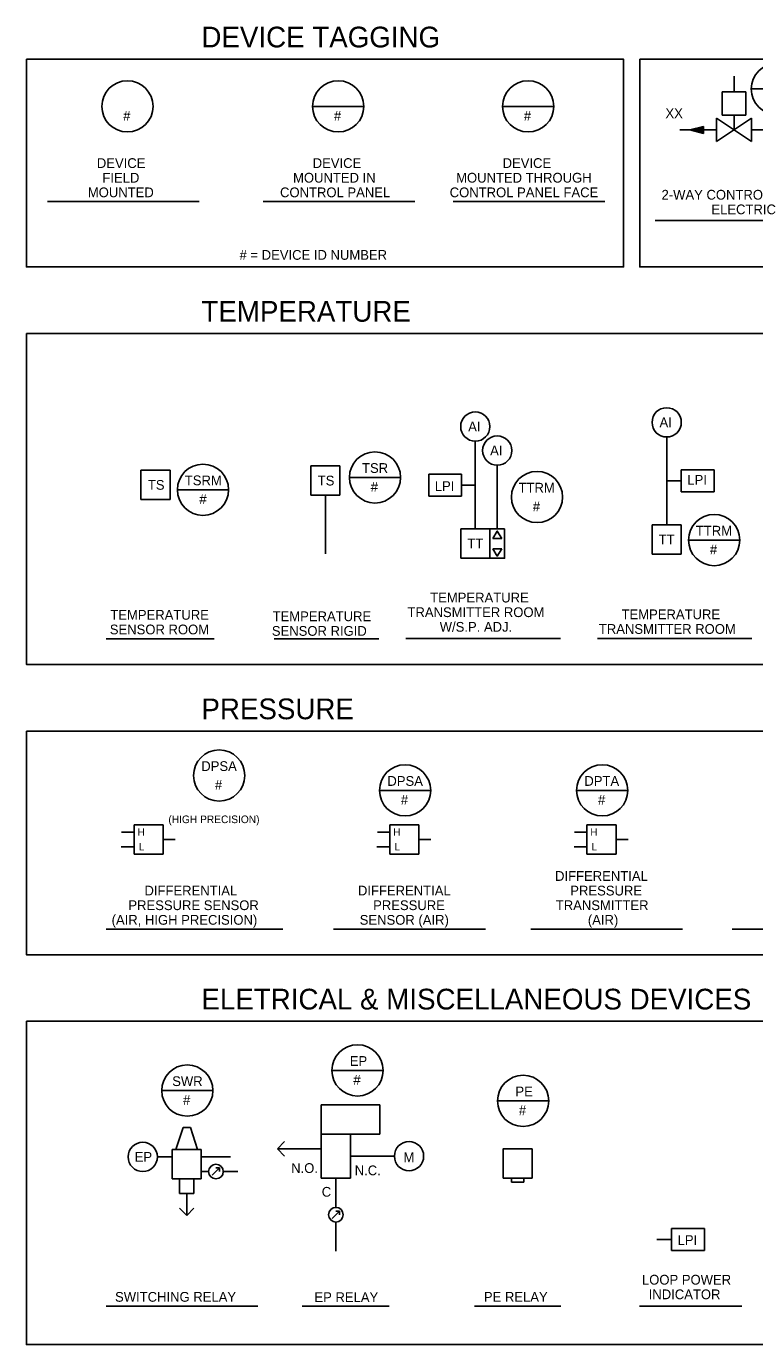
# Model space of a CAD drawing. Extents: x 10015 to 10283, y 10002 to 10184.
# Drawn here: x 10015.5 to 10065.3, y 10089.9 to 10180 of the extents above; entities that cross this region are included whole.
import ezdxf

# ---------------------------------------------------------------- set-up
doc = ezdxf.new("R2010")
doc.units = 0
for name, color, linetype in [('G-ANNO-TEXT', 7, 'Continuous'), ('G-DETL-LINE', 7, 'Continuous'), ('G-DETL-TEXT', 7, 'Continuous'), ('M-ANNO-NPLT', 7, 'Continuous')]:
    doc.layers.add(name, color=color, linetype=linetype)

msp = doc.modelspace()

# ---------------------------------------------------------------- linework, layer by layer
at = {"layer": 'G-ANNO-TEXT'}
for p, q in [((10016.93, 10168.02), (10027.299, 10168.02)), ((10031.683, 10168.02), (10042.051, 10168.02)), ((10044.663, 10168.02), (10055.032, 10168.02)), ((10058.48, 10166.726), (10071.068, 10166.726)), ((10020.949, 10138.131), (10028.33, 10138.131)), ((10032.443, 10138.131), (10039.578, 10138.131)), ((10041.442, 10138.166), (10052.007, 10138.166)), ((10054.521, 10138.166), (10065.086, 10138.166)), ((10020.949, 10118.291), (10033.029, 10118.291)), ((10036.499, 10118.291), (10046.867, 10118.291)), ((10049.974, 10118.291), (10060.342, 10118.291)), ((10063.729, 10118.291), (10074.097, 10118.291)), ((10020.949, 10092.522), (10031.317, 10092.522)), ((10034.344, 10092.522), (10040.291, 10092.522)), ((10046.125, 10092.522), (10052.027, 10092.522)), ((10057.408, 10092.522), (10064.404, 10092.522))]:
    msp.add_line(p, q, dxfattribs=at)
at = {"layer": 'G-DETL-LINE'}
for p, q in [((10063.063, 10173.927), (10063.063, 10175.527)), ((10063.063, 10175.527), (10064.663, 10175.527)), ((10064.663, 10175.527), (10064.663, 10173.927)), ((10062.663, 10173.725), (10065.063, 10172.125)), ((10062.663, 10172.125), (10062.663, 10173.725)), ((10062.663, 10172.125), (10065.063, 10173.725)), ((10063.063, 10173.927), (10064.663, 10173.927)), ((10063.863, 10173.927), (10063.863, 10172.925)), ((10065.063, 10173.725), (10065.063, 10172.125)), ((10062.663, 10172.925), (10060.153, 10172.925)), ((10061.768, 10172.92), (10060.835, 10172.92)), ((10061.768, 10172.961), (10061.013, 10172.961)), ((10061.768, 10172.878), (10061.013, 10172.878)), ((10061.768, 10173.003), (10061.184, 10173.003)), ((10061.768, 10172.836), (10061.184, 10172.836)), ((10061.768, 10173.045), (10061.351, 10173.045)), ((10061.768, 10172.795), (10061.351, 10172.795)), ((10061.768, 10173.086), (10061.515, 10173.086)), ((10061.768, 10172.753), (10061.515, 10172.753)), ((10061.768, 10173.128), (10061.667, 10173.128)), ((10061.768, 10172.711), (10061.667, 10172.711)), ((10067.269, 10172.925), (10065.063, 10172.925)), ((10059.26, 10145.934), (10059.26, 10151.934)), ((10046.181, 10145.647), (10046.181, 10151.647)), ((10034.93, 10149.953), (10034.93, 10147.953)), ((10036.93, 10149.953), (10034.93, 10149.953)), ((10036.93, 10147.953), (10036.93, 10149.953)), ((10047.681, 10145.647), (10047.681, 10150.006)), ((10023.319, 10149.659), (10023.319, 10147.659)), ((10025.319, 10149.659), (10023.319, 10149.659)), ((10025.319, 10147.659), (10025.319, 10149.659)), ((10042.996, 10149.396), (10045.246, 10149.396)), ((10042.996, 10147.896), (10042.996, 10149.396)), ((10045.246, 10149.396), (10045.246, 10147.896)), ((10062.51, 10149.684), (10060.26, 10149.684)), ((10060.26, 10149.684), (10060.26, 10148.184)), ((10062.51, 10148.184), (10062.51, 10149.684)), ((10045.246, 10148.646), (10046.181, 10148.646)), ((10059.26, 10148.934), (10060.26, 10148.934)), ((10060.26, 10148.184), (10062.51, 10148.184)), ((10023.319, 10147.659), (10025.319, 10147.659)), ((10034.93, 10147.953), (10036.93, 10147.953)), ((10035.93, 10143.953), (10035.93, 10147.953)), ((10045.246, 10147.896), (10042.996, 10147.896)), ((10045.181, 10145.647), (10045.181, 10143.647)), ((10047.181, 10145.647), (10045.181, 10145.647)), ((10047.181, 10143.647), (10047.181, 10145.647)), ((10047.181, 10145.647), (10048.181, 10145.647)), ((10058.26, 10145.934), (10058.26, 10143.934)), ((10060.26, 10145.934), (10058.26, 10145.934)), ((10060.26, 10143.934), (10060.26, 10145.934)), ((10047.381, 10145), (10047.995, 10145)), ((10045.181, 10143.647), (10047.181, 10143.647)), ((10047.381, 10144.293), (10047.995, 10144.293)), ((10058.26, 10143.934), (10060.26, 10143.934)), ((10022.854, 10124.927), (10022.006, 10124.927)), ((10022.854, 10123.427), (10022.854, 10125.427)), ((10022.854, 10125.427), (10024.854, 10125.427)), ((10024.854, 10125.427), (10024.854, 10123.427)), ((10040.331, 10124.927), (10039.484, 10124.927)), ((10040.331, 10123.427), (10040.331, 10125.427)), ((10040.331, 10125.427), (10042.331, 10125.427)), ((10042.331, 10125.427), (10042.331, 10123.427)), ((10053.806, 10124.927), (10052.959, 10124.927)), ((10053.806, 10123.427), (10053.806, 10125.427)), ((10053.806, 10125.427), (10055.806, 10125.427)), ((10055.806, 10125.427), (10055.806, 10123.427)), ((10022.854, 10123.927), (10021.976, 10123.927)), ((10024.854, 10124.427), (10025.669, 10124.427)), ((10040.331, 10123.927), (10039.454, 10123.927)), ((10042.331, 10124.427), (10043.147, 10124.427)), ((10053.806, 10123.927), (10052.928, 10123.927)), ((10055.806, 10124.427), (10056.622, 10124.427)), ((10024.854, 10123.427), (10022.854, 10123.427)), ((10042.331, 10123.427), (10040.331, 10123.427)), ((10055.806, 10123.427), (10053.806, 10123.427)), ((10035.649, 10106.273), (10035.649, 10101.273)), ((10039.649, 10106.273), (10035.649, 10106.273)), ((10039.649, 10104.273), (10039.649, 10106.273)), ((10025.703, 10103.223), (10026.203, 10104.723)), ((10026.203, 10104.723), (10026.703, 10104.723)), ((10026.703, 10104.723), (10027.203, 10103.223)), ((10035.649, 10104.273), (10039.649, 10104.273)), ((10037.649, 10101.273), (10037.649, 10104.273)), ((10027.453, 10103.223), (10025.453, 10103.223)), ((10025.453, 10103.223), (10025.453, 10101.223)), ((10027.453, 10101.223), (10027.453, 10103.223)), ((10033.149, 10103.773), (10032.649, 10103.273)), ((10032.649, 10103.273), (10033.149, 10102.773)), ((10035.649, 10103.273), (10032.649, 10103.273)), ((10050.076, 10103.273), (10050.076, 10101.273)), ((10025.453, 10102.723), (10024.453, 10102.723)), ((10027.453, 10102.723), (10029.453, 10102.723)), ((10037.649, 10102.773), (10040.649, 10102.773)), ((10027.453, 10101.723), (10027.953, 10101.723)), ((10028.203, 10101.473), (10028.703, 10101.973)), ((10028.453, 10101.973), (10028.703, 10101.973)), ((10028.703, 10101.973), (10028.703, 10101.723)), ((10028.953, 10101.723), (10029.953, 10101.723)), ((10035.649, 10101.273), (10037.649, 10101.273)), ((10036.649, 10101.273), (10036.649, 10099.273)), ((10050.076, 10101.273), (10048.076, 10101.273)), ((10048.657, 10101.273), (10048.657, 10100.997)), ((10025.453, 10101.223), (10027.453, 10101.223)), ((10025.953, 10101.223), (10025.953, 10100.223)), ((10026.953, 10100.223), (10026.953, 10101.223)), ((10025.953, 10100.223), (10026.953, 10100.223)), ((10026.453, 10100.223), (10026.453, 10098.723)), ((10025.953, 10099.223), (10026.453, 10098.723)), ((10026.453, 10098.723), (10026.953, 10099.223)), ((10036.399, 10098.523), (10036.899, 10099.023)), ((10036.649, 10099.023), (10036.899, 10099.023)), ((10036.899, 10099.023), (10036.899, 10098.773)), ((10036.649, 10096.273), (10036.649, 10098.273)), ((10061.838, 10097.834), (10059.588, 10097.834)), ((10059.588, 10097.834), (10059.588, 10096.334)), ((10061.838, 10096.334), (10061.838, 10097.834)), ((10058.588, 10097.084), (10059.588, 10097.084)), ((10059.588, 10096.334), (10061.838, 10096.334))]:
    msp.add_line(p, q, dxfattribs=at)
for points in [[(10015.495, 10177.757), (10056.315, 10177.757), (10056.315, 10163.559), (10015.495, 10163.559)], [(10057.424, 10177.757), (10126.391, 10177.757), (10126.391, 10163.559), (10057.424, 10163.559)], [(10061.768, 10172.686), (10060.835, 10172.92), (10061.768, 10173.153)], [(10015.495, 10159.007), (10161.797, 10159.007), (10161.797, 10136.385), (10015.495, 10136.385)], [(10015.495, 10131.834), (10130.67, 10131.834), (10130.67, 10116.546), (10015.495, 10116.546)], [(10015.495, 10111.994), (10130.67, 10111.994), (10130.67, 10089.891), (10015.495, 10089.891)]]:
    msp.add_lwpolyline(points, close=True, dxfattribs=at)
for points in [[(10048.181, 10145.647), (10048.181, 10143.647), (10047.181, 10143.647)], [(10047.381, 10145), (10047.681, 10145.496), (10047.995, 10145)], [(10047.381, 10144.293), (10047.681, 10143.797), (10047.995, 10144.293)], [(10048.076, 10101.273), (10048.076, 10103.273), (10050.076, 10103.273)], [(10048.657, 10100.997), (10049.496, 10100.997), (10049.496, 10101.273)]]:
    msp.add_lwpolyline(points, dxfattribs=at)
for centre, radius in [((10046.181, 10152.647), 1), ((10059.26, 10152.934), 1), ((10047.681, 10151.006), 1), ((10023.453, 10102.723), 1), ((10041.649, 10102.773), 1), ((10028.453, 10101.723), 0.5), ((10036.649, 10098.773), 0.5)]:
    msp.add_circle(centre, radius, dxfattribs=at)
at = {"layer": 'G-DETL-TEXT'}
for p, q in [((10035.059, 10174.53), (10038.559, 10174.53)), ((10048.039, 10174.53), (10051.539, 10174.53)), ((10036.382, 10108.636), (10039.882, 10108.636)), ((10024.744, 10107.257), (10028.244, 10107.257)), ((10047.697, 10106.55), (10051.197, 10106.55))]:
    msp.add_line(p, q, dxfattribs=at)
for centre in [(10066.793, 10175.719), (10022.403, 10174.53), (10036.809, 10174.53), (10049.789, 10174.53), (10039.324, 10149.168), (10027.566, 10148.325), (10050.401, 10147.826), (10062.506, 10144.886), (10028.673, 10128.793), (10041.381, 10127.778), (10054.855, 10127.778), (10038.132, 10108.636), (10026.494, 10107.257), (10049.447, 10106.55)]:
    msp.add_circle(centre, 1.75, dxfattribs=at)
at = {"layer": 'M-ANNO-NPLT'}
for p, q in [((10063.863, 10175.527), (10063.863, 10176.591)), ((10065.043, 10175.719), (10068.543, 10175.719)), ((10037.574, 10149.168), (10041.074, 10149.168)), ((10025.816, 10148.325), (10029.316, 10148.325)), ((10060.756, 10144.886), (10064.256, 10144.886)), ((10039.631, 10127.778), (10043.131, 10127.778)), ((10053.105, 10127.778), (10056.605, 10127.778))]:
    msp.add_line(p, q, dxfattribs=at)

# ---------------------------------------------------------------- texts
at = {"layer": 'G-ANNO-TEXT'}
for s, height, p in [('DEVICE TAGGING', 1.41667, (10027.46, 10178.562)), ('XX', 0.6667, (10059.176, 10173.725)), ('DEVICE', 0.6667, (10020.314, 10170.321)), ('DEVICE', 0.6667, (10035.066, 10170.321)), ('DEVICE', 0.6667, (10048.047, 10170.321)), ('FIELD', 0.6667, (10020.694, 10169.321)), ('MOUNTED IN', 0.6667, (10033.723, 10169.321)), ('MOUNTED THROUGH', 0.66667, (10044.87, 10169.321)), ('MOUNTED', 0.6667, (10019.697, 10168.321)), ('CONTROL PANEL', 0.66667, (10032.834, 10168.321)), ('CONTROL PANEL FACE', 0.66667, (10044.43, 10168.321)), ('2-WAY CONTROL VALVE', 0.66667, (10058.91, 10168.157)), ('ELECTRIC', 0.6667, (10062.318, 10167.157)), ('# = DEVICE ID NUMBER', 0.66667, (10030.068, 10164.045)), ('TEMPERATURE', 1.41667, (10027.46, 10159.813)), ('TEMPERATURE', 0.66667, (10043.097, 10140.622)), ('TEMPERATURE', 0.66667, (10021.235, 10139.442)), ('TEMPERATURE', 0.66667, (10032.328, 10139.343)), ('TRANSMITTER ROOM', 0.66667, (10041.545, 10139.622)), ('TEMPERATURE', 0.66667, (10056.176, 10139.477)), ('SENSOR ROOM', 0.66667, (10021.199, 10138.442)), ('W/S.P. ADJ.', 0.66667, (10043.749, 10138.622)), ('TRANSMITTER ROOM', 0.66667, (10054.624, 10138.477)), ('SENSOR RIGID', 0.66667, (10032.274, 10138.343)), ('PRESSURE', 1.4167, (10027.46, 10132.639)), ('DIFFERENTIAL', 0.66667, (10051.632, 10121.593)), ('DIFFERENTIAL', 0.66667, (10023.568, 10120.593)), ('DIFFERENTIAL', 0.66667, (10038.158, 10120.593)), ('PRESSURE', 0.6667, (10052.672, 10120.593)), ('PRESSURE SENSOR', 0.66667, (10022.468, 10119.593)), ('PRESSURE', 0.6667, (10039.197, 10119.593)), ('TRANSMITTER', 0.66667, (10051.682, 10119.593)), ('(AIR, HIGH PRECISION)', 0.66667, (10021.322, 10118.593)), ('SENSOR (AIR)', 0.66667, (10038.28, 10118.593)), ('(AIR)', 0.6667, (10053.872, 10118.593)), ('ELETRICAL & MISCELLANEOUS DEVICES', 1.41667, (10027.46, 10112.8)), ('LOOP POWER ', 0.66667, (10057.572, 10093.995)), ('SWITCHING RELAY', 0.66667, (10021.558, 10092.823)), ('EP RELAY', 0.6667, (10035.184, 10092.803)), ('PE RELAY', 0.6667, (10046.767, 10092.823)), ('INDICATOR', 0.6667, (10058.033, 10092.995))]:
    msp.add_text(s, height=height, dxfattribs=at).set_placement(p)
at = {"layer": 'G-DETL-LINE'}
for s, height, p in [('AI', 0.6667, (10045.693, 10152.313)), ('AI', 0.6667, (10058.772, 10152.6)), ('AI', 0.6667, (10047.193, 10150.673)), ('TS', 0.6667, (10035.412, 10148.619)), ('LPI', 0.6667, (10060.673, 10148.67)), ('TS', 0.6667, (10023.801, 10148.326)), ('LPI', 0.6667, (10043.41, 10148.244)), ('TT', 0.6667, (10045.639, 10144.313)), ('TT', 0.6667, (10058.718, 10144.6)), ('(HIGH PRECISION)', 0.52083, (10025.201, 10125.538)), ('H', 0.5, (10023.098, 10124.677)), ('H', 0.5, (10040.576, 10124.677)), ('H', 0.5, (10054.05, 10124.677)), ('L', 0.5, (10023.183, 10123.677)), ('L', 0.5, (10040.66, 10123.677)), ('L', 0.5, (10054.135, 10123.677)), ('EP', 0.6667, (10022.901, 10102.39)), ('N.O.', 0.6667, (10033.594, 10101.627)), ('M', 0.667, (10041.271, 10102.362)), ('N.C.', 0.6667, (10037.94, 10101.47)), ('C', 0.667, (10035.684, 10100.003)), ('LPI', 0.6667, (10060.007, 10096.706))]:
    msp.add_text(s, height=height, dxfattribs=at).set_placement(p)
at = {"layer": 'G-DETL-TEXT'}
for s, height, p in [('#', 0.667, (10022.113, 10173.555)), ('#', 0.667, (10036.519, 10173.555)), ('#', 0.667, (10049.499, 10173.555)), ('TSR', 0.6667, (10038.437, 10149.477)), ('TSRM', 0.6667, (10026.326, 10148.633)), ('#', 0.667, (10039.033, 10148.193)), ('TTRM', 0.6667, (10049.136, 10148.135)), ('#', 0.667, (10027.317, 10147.349)), ('#', 0.667, (10050.11, 10146.851)), ('TTRM', 0.6667, (10061.254, 10145.195)), ('#', 0.667, (10062.216, 10143.91)), ('DPSA', 0.6667, (10027.452, 10129.102)), ('#', 0.667, (10028.383, 10127.818)), ('DPSA', 0.6667, (10040.171, 10128.087)), ('DPTA', 0.6667, (10053.634, 10128.087)), ('#', 0.667, (10041.091, 10126.803)), ('#', 0.667, (10054.565, 10126.803)), ('EP', 0.6667, (10037.601, 10108.945)), ('SWR', 0.6667, (10025.463, 10107.566)), ('#', 0.667, (10037.842, 10107.661)), ('#', 0.667, (10026.204, 10106.282)), ('PE', 0.6667, (10048.922, 10106.859)), ('#', 0.667, (10049.157, 10105.574))]:
    msp.add_text(s, height=height, dxfattribs=at).set_placement(p)

doc.saveas('drawing.dxf')
